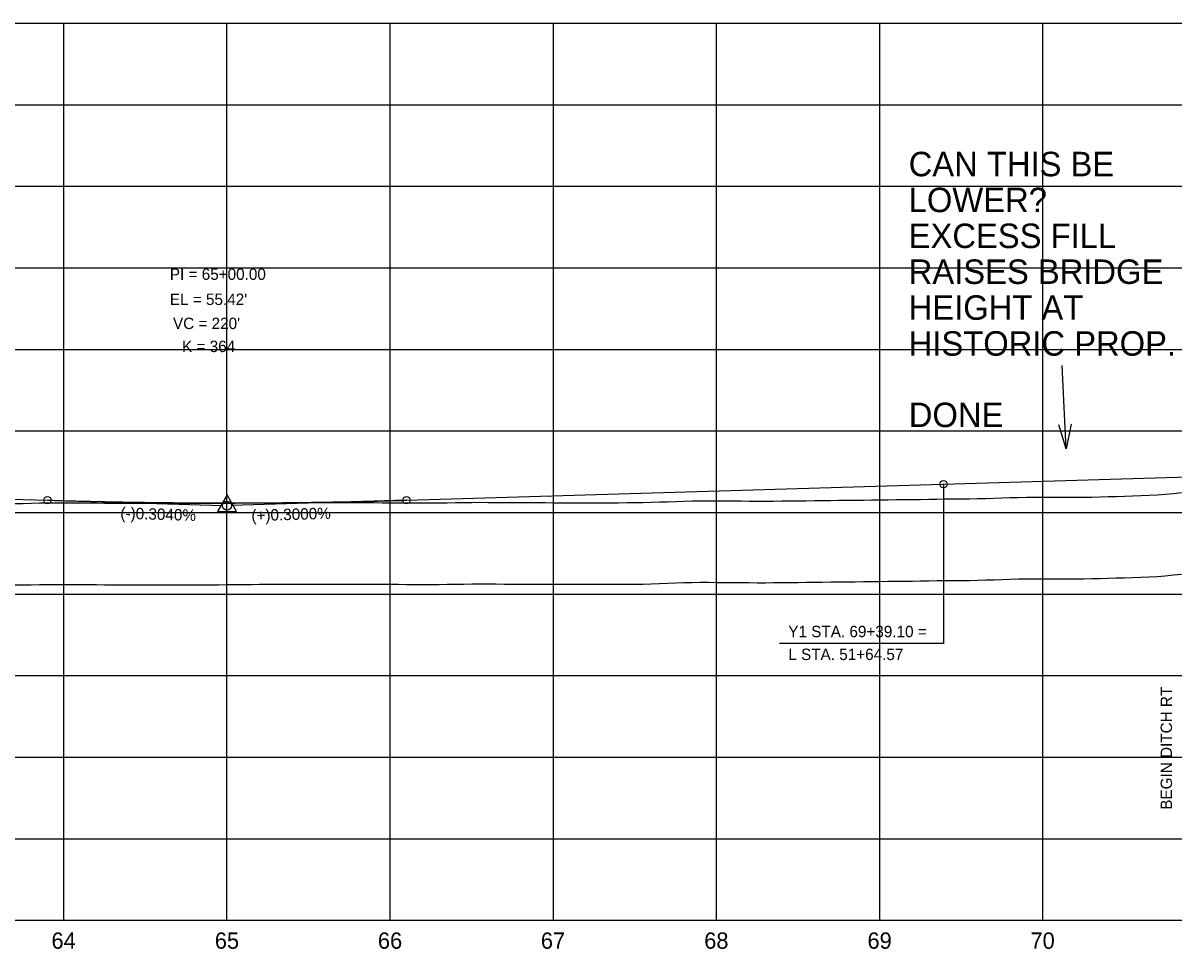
# Model space of a CAD drawing. Extents: x 2345490 to 2436403, y 465165 to 573888.
# Drawn here: x 2386697 to 2387402, y 557766 to 558334 of the extents above; entities that cross this region are included whole.
import ezdxf

# ---------------------------------------------------------------- set-up
doc = ezdxf.new("R2010")
doc.units = 0
for name, color, linetype in [('Old_Level_1', 7, 'Continuous'), ('Old_Level_2', 7, 'Continuous'), ('Old_Level_3', 7, 'Continuous'), ('Old_Level_57', 7, 'Continuous'), ('Old_Level_62', 7, 'Continuous'), ('Old_Level_63', 7, 'Continuous')]:
    doc.layers.add(name, color=color, linetype=linetype)

msp = doc.modelspace()

# ---------------------------------------------------------------- linework, layer by layer
at = {"layer": 'Old_Level_1'}
for points in [[(2387321.5425, 557993.43925), (2387326.5425, 557993.45375), (2387331.5425, 557993.47075), (2387336.5425, 557993.488), (2387341.5425, 557993.50525), (2387346.5425, 557993.52275), (2387351.5425, 557993.57775), (2387356.5425, 557993.6995), (2387361.5425, 557993.82175), (2387366.5425, 557993.944), (2387371.5425, 557994.09075), (2387376.5425, 557994.26875), (2387381.5425, 557994.44675), (2387386.5425, 557994.62475), (2387391.5425, 557994.88725), (2387396.5425, 557995.361), (2387401.5425, 557995.835), (2387406.5425, 557996.285)], [(2386691.5425, 557989.696), (2386696.5425, 557989.68025), (2386701.5425, 557989.834), (2386706.5425, 557989.99575), (2386711.5425, 557990.04875), (2386716.5425, 557990.04025), (2386721.5425, 557990.032), (2386726.5425, 557990.0235), (2386731.5425, 557990.015), (2386736.5425, 557989.99125), (2386741.5425, 557989.91625), (2386746.5425, 557989.84125), (2386751.5425, 557989.80225), (2386756.5425, 557989.784), (2386761.5425, 557989.766), (2386766.5425, 557989.748), (2386771.5425, 557989.73), (2386776.5425, 557989.7305), (2386781.5425, 557989.75425), (2386786.5425, 557989.778), (2386791.5425, 557989.7915), (2386796.5425, 557989.799), (2386801.5425, 557989.80675), (2386806.5425, 557989.8145), (2386811.5425, 557989.822), (2386816.5425, 557989.8345), (2386821.5425, 557989.8505)], [(2386821.5425, 557989.8505), (2386826.5425, 557989.86675), (2386831.5425, 557989.9185), (2386836.5425, 557989.991), (2386841.5425, 557990.06375), (2386846.5425, 557990.0945), (2386851.5425, 557990.10275), (2386856.5425, 557990.111), (2386861.5425, 557990.119), (2386866.5425, 557990.127), (2386871.5425, 557990.13), (2386876.5425, 557990.12975), (2386881.5425, 557990.1295), (2386886.5425, 557990.12925), (2386891.5425, 557990.129), (2386896.5425, 557990.13325), (2386901.5425, 557990.14075), (2386906.5425, 557990.148), (2386911.5425, 557990.135), (2386916.5425, 557990.11), (2386921.5425, 557990.08475), (2386926.5425, 557990.0595), (2386931.5425, 557990.03425), (2386936.5425, 557990.00875), (2386941.5425, 557989.9835), (2386946.5425, 557989.958), (2386951.5425, 557989.9935), (2386956.5425, 557990.065), (2386961.5425, 557990.1365), (2386966.5425, 557990.208), (2386971.5425, 557990.27925), (2386976.5425, 557990.32575), (2386981.5425, 557990.29525), (2386986.5425, 557990.2645), (2386991.5425, 557990.239), (2386996.5425, 557990.21675), (2387001.5425, 557990.1945), (2387006.5425, 557990.17225), (2387011.5425, 557990.15025), (2387016.5425, 557990.12825), (2387021.5425, 557990.10625), (2387026.5425, 557990.08425), (2387031.5425, 557990.0775), (2387036.5425, 557990.08025), (2387041.5425, 557990.083), (2387046.5425, 557990.08575), (2387051.5425, 557990.0885), (2387056.5425, 557990.09125), (2387061.5425, 557990.1145), (2387066.5425, 557990.156), (2387071.5425, 557990.1825), (2387076.5425, 557990.1995), (2387081.5425, 557990.362), (2387086.5425, 557990.542), (2387091.5425, 557990.7225), (2387096.5425, 557990.903), (2387101.5425, 557991.08375), (2387106.5425, 557991.26475), (2387111.5425, 557991.31775), (2387116.5425, 557991.2835), (2387121.5425, 557991.24975), (2387126.5425, 557991.216), (2387131.5425, 557991.18275), (2387136.5425, 557991.1495), (2387141.5425, 557991.1165), (2387146.5425, 557991.043), (2387151.5425, 557991.02075), (2387156.5425, 557991.083), (2387161.5425, 557991.1455), (2387166.5425, 557991.2085), (2387171.5425, 557991.27175), (2387176.5425, 557991.33525), (2387181.5425, 557991.39925), (2387186.5425, 557991.4635), (2387191.5425, 557991.5285), (2387196.5425, 557991.57175), (2387201.5425, 557991.62875), (2387206.5425, 557991.686), (2387211.5425, 557991.74375), (2387216.5425, 557991.802), (2387221.5425, 557991.8605), (2387226.5425, 557991.91975), (2387231.5425, 557991.9585), (2387236.5425, 557992.01875), (2387241.5425, 557992.0895), (2387246.5425, 557992.16075), (2387251.5425, 557992.23225), (2387256.5425, 557992.30425), (2387261.5425, 557992.3765), (2387266.5425, 557992.44925), (2387271.5425, 557992.4885), (2387276.5425, 557992.49), (2387281.5425, 557992.60775), (2387286.5425, 557992.75225), (2387291.5425, 557992.897), (2387296.5425, 557993.042), (2387301.5425, 557993.187), (2387306.5425, 557993.332), (2387311.5425, 557993.42025), (2387316.5425, 557993.42975), (2387321.5425, 557993.43925)]]:
    msp.add_lwpolyline(points, dxfattribs=at)
at = {"layer": 'Old_Level_2'}
for p, q in [((2386931.5425, 558041.61275), (2387441.5425, 558056.91275)), ((2386681.5425, 558042.569), (2386711.5425, 558041.65675)), ((2386711.5425, 558041.65675), (2386818.794, 558038.39625)), ((2386931.5425, 558041.61275), (2386824.2915, 558038.395))]:
    msp.add_line(p, q, dxfattribs=at)
msp.add_lwpolyline([(2386815.67725, 558034.739), (2386827.41975, 558034.739), (2386821.54875, 558044.86475)], close=True, dxfattribs=at)
for centre, radius in [((2387260.6425, 558051.48575), 2.25), ((2386711.5425, 558041.65675), 2.25), ((2386931.5425, 558041.61275), 2.25), ((2386821.5425, 558038.31275), 2.75)]:
    msp.add_circle(centre, radius, dxfattribs=at)
msp.add_spline([(2386711.5425, 558041.65675), (2386715.9425, 558041.52575), (2386720.3425, 558041.4), (2386724.7425, 558041.2795), (2386729.1425, 558041.16425), (2386733.5425, 558041.0545), (2386737.9425, 558040.95), (2386742.3425, 558040.85075), (2386746.7425, 558040.757), (2386751.1425, 558040.66825), (2386755.5425, 558040.585), (2386759.9425, 558040.507), (2386764.3425, 558040.4345), (2386768.7425, 558040.36725), (2386773.1425, 558040.305), (2386777.5425, 558040.2485), (2386781.9425, 558040.197), (2386786.3425, 558040.151), (2386790.7425, 558040.11025), (2386795.1425, 558040.07475), (2386799.5425, 558040.04475), (2386803.9425, 558040.02), (2386808.3425, 558040.0005), (2386812.7425, 558039.98625), (2386817.1425, 558039.9775), (2386821.5425, 558039.97375), (2386825.9425, 558039.97575), (2386830.3425, 558039.98275), (2386834.7425, 558039.99525), (2386839.1425, 558040.013), (2386843.5425, 558040.036), (2386847.9425, 558040.06425), (2386852.3425, 558040.098), (2386856.7425, 558040.137), (2386861.1425, 558040.18125), (2386865.5425, 558040.23075), (2386869.9425, 558040.28575), (2386874.3425, 558040.346), (2386878.7425, 558040.4115), (2386883.1425, 558040.4825), (2386887.5425, 558040.55875), (2386891.9425, 558040.64025), (2386896.3425, 558040.727), (2386900.7425, 558040.819), (2386905.1425, 558040.9165), (2386909.5425, 558041.01925), (2386913.9425, 558041.1275), (2386918.3425, 558041.24075), (2386922.7425, 558041.3595), (2386927.1425, 558041.4835), (2386931.5425, 558041.61275)], degree=3, dxfattribs=at)
at = {"layer": 'Old_Level_3'}
for p, q in [((2387260.6425, 558051.48575), (2387260.6425, 557953.83025)), ((2387260.6425, 557953.83025), (2387160.07325, 557953.83025))]:
    msp.add_line(p, q, dxfattribs=at)
at = {"layer": 'Old_Level_57'}
for p, q in [((2381271.54275, 558334.11325), (2393041.55275, 558334.11325)), ((2386721.54225, 557784.21325), (2386721.54225, 558334.21325)), ((2386721.54225, 557784.11325), (2386721.54225, 558334.11325)), ((2386821.54225, 557784.21325), (2386821.54225, 558334.21325)), ((2386821.54225, 557784.11325), (2386821.54225, 558334.11325)), ((2386921.54225, 557784.21325), (2386921.54225, 558334.21325)), ((2386921.54225, 557784.11325), (2386921.54225, 558334.11325)), ((2387021.54225, 557784.21325), (2387021.54225, 558334.21325)), ((2387021.54225, 557784.11325), (2387021.54225, 558334.11325)), ((2387121.54225, 557784.21325), (2387121.54225, 558334.21325)), ((2387121.54225, 557784.11325), (2387121.54225, 558334.11325)), ((2387221.54225, 557784.21325), (2387221.54225, 558334.21325)), ((2387221.54225, 557784.11325), (2387221.54225, 558334.11325)), ((2387321.54225, 557784.21325), (2387321.54225, 558334.21325)), ((2387321.54225, 557784.11325), (2387321.54225, 558334.11325)), ((2381271.54275, 558284.11325), (2393041.55275, 558284.11325)), ((2381271.54275, 558234.11325), (2393041.55275, 558234.11325)), ((2381271.54275, 558184.11325), (2393041.55275, 558184.11325)), ((2381271.54275, 558134.11325), (2393041.55275, 558134.11325)), ((2381271.54275, 558084.11325), (2393041.55275, 558084.11325)), ((2381271.5425, 558034.11325), (2393041.55275, 558034.11325)), ((2381271.54275, 557984.11325), (2393041.55275, 557984.11325)), ((2381271.5425, 557934.11325), (2393041.55275, 557934.11325)), ((2381271.54275, 557884.11325), (2393041.55275, 557884.11325)), ((2381271.5425, 557834.11325), (2393041.55275, 557834.11325)), ((2381271.54275, 557784.11325), (2393041.55275, 557784.11325))]:
    msp.add_line(p, q, dxfattribs=at)
at = {"layer": 'Old_Level_62'}
for points in [[(2387321.5425, 558043.44525), (2387326.5425, 558043.45975), (2387331.5425, 558043.47675), (2387336.5425, 558043.494), (2387341.5425, 558043.51125), (2387346.5425, 558043.52875), (2387351.5425, 558043.58375), (2387356.5425, 558043.7055), (2387361.5425, 558043.82775), (2387366.5425, 558043.95), (2387371.5425, 558044.09675), (2387376.5425, 558044.27475), (2387381.5425, 558044.45275), (2387386.5425, 558044.63075), (2387391.5425, 558044.89325), (2387396.5425, 558045.367), (2387401.5425, 558045.841), (2387406.5425, 558046.291)], [(2386691.5425, 558039.702), (2386696.5425, 558039.68625), (2386701.5425, 558039.84), (2386706.5425, 558040.00175), (2386711.5425, 558040.05475), (2386716.5425, 558040.04625), (2386721.5425, 558040.038), (2386726.5425, 558040.0295), (2386731.5425, 558040.021), (2386736.5425, 558039.99725), (2386741.5425, 558039.92225), (2386746.5425, 558039.84725), (2386751.5425, 558039.80825), (2386756.5425, 558039.79), (2386761.5425, 558039.772), (2386766.5425, 558039.754), (2386771.5425, 558039.736), (2386776.5425, 558039.7365), (2386781.5425, 558039.76025), (2386786.5425, 558039.784), (2386791.5425, 558039.7975), (2386796.5425, 558039.805), (2386801.5425, 558039.81275), (2386806.5425, 558039.8205), (2386811.5425, 558039.828), (2386816.5425, 558039.8405), (2386821.5425, 558039.8565)], [(2386821.5425, 558039.8565), (2386826.5425, 558039.87275), (2386831.5425, 558039.9245), (2386836.5425, 558039.997), (2386841.5425, 558040.06975), (2386846.5425, 558040.1005), (2386851.5425, 558040.10875), (2386856.5425, 558040.117), (2386861.5425, 558040.125), (2386866.5425, 558040.133), (2386871.5425, 558040.136), (2386876.5425, 558040.13575), (2386881.5425, 558040.1355), (2386886.5425, 558040.13525), (2386891.5425, 558040.135), (2386896.5425, 558040.13925), (2386901.5425, 558040.14675), (2386906.5425, 558040.154), (2386911.5425, 558040.141), (2386916.5425, 558040.116), (2386921.5425, 558040.09075), (2386926.5425, 558040.0655), (2386931.5425, 558040.04025), (2386936.5425, 558040.01475), (2386941.5425, 558039.9895), (2386946.5425, 558039.964), (2386951.5425, 558039.9995), (2386956.5425, 558040.071), (2386961.5425, 558040.1425), (2386966.5425, 558040.214), (2386971.5425, 558040.28525), (2386976.5425, 558040.33175), (2386981.5425, 558040.30125), (2386986.5425, 558040.2705), (2386991.5425, 558040.245), (2386996.5425, 558040.22275), (2387001.5425, 558040.2005), (2387006.5425, 558040.17825), (2387011.5425, 558040.15625), (2387016.5425, 558040.13425), (2387021.5425, 558040.11225), (2387026.5425, 558040.09025), (2387031.5425, 558040.0835), (2387036.5425, 558040.08625), (2387041.5425, 558040.089), (2387046.5425, 558040.09175), (2387051.5425, 558040.0945), (2387056.5425, 558040.09725), (2387061.5425, 558040.1205), (2387066.5425, 558040.162), (2387071.5425, 558040.1885), (2387076.5425, 558040.2055), (2387081.5425, 558040.368), (2387086.5425, 558040.548), (2387091.5425, 558040.7285), (2387096.5425, 558040.909), (2387101.5425, 558041.08975), (2387106.5425, 558041.27075), (2387111.5425, 558041.32375), (2387116.5425, 558041.2895), (2387121.5425, 558041.25575), (2387126.5425, 558041.222), (2387131.5425, 558041.18875), (2387136.5425, 558041.1555), (2387141.5425, 558041.1225), (2387146.5425, 558041.049), (2387151.5425, 558041.02675), (2387156.5425, 558041.089), (2387161.5425, 558041.1515), (2387166.5425, 558041.2145), (2387171.5425, 558041.27775), (2387176.5425, 558041.34125), (2387181.5425, 558041.40525), (2387186.5425, 558041.4695), (2387191.5425, 558041.5345), (2387196.5425, 558041.57775), (2387201.5425, 558041.63475), (2387206.5425, 558041.692), (2387211.5425, 558041.74975), (2387216.5425, 558041.808), (2387221.5425, 558041.8665), (2387226.5425, 558041.92575), (2387231.5425, 558041.9645), (2387236.5425, 558042.02475), (2387241.5425, 558042.0955), (2387246.5425, 558042.16675), (2387251.5425, 558042.23825), (2387256.5425, 558042.31025), (2387261.5425, 558042.3825), (2387266.5425, 558042.45525), (2387271.5425, 558042.4945), (2387276.5425, 558042.496), (2387281.5425, 558042.61375), (2387286.5425, 558042.75825), (2387291.5425, 558042.903), (2387296.5425, 558043.048), (2387301.5425, 558043.193), (2387306.5425, 558043.338), (2387311.5425, 558043.42625), (2387316.5425, 558043.43575), (2387321.5425, 558043.44525)]]:
    msp.add_lwpolyline(points, dxfattribs=at)
at = {"layer": 'Old_Level_63'}
for p, q in [((2387335.7365, 558073.02975), (2387333.4405, 558124.324)), ((2381321.5425, 557784.113), (2393019.104, 557784.113))]:
    msp.add_line(p, q, dxfattribs=at)
msp.add_lwpolyline([(2387338.812, 558088.1825), (2387335.7365, 558073.02975), (2387331.3195, 558087.847)], dxfattribs=at)

# ---------------------------------------------------------------- texts
at = {"layer": 'Old_Level_1'}
for s, p in [('64', (2386713.994, 557766.613)), ('65', (2386814.0865, 557766.613)), ('66', (2386914.0275, 557766.613)), ('67', (2387013.885, 557766.613)), ('68', (2387114.01075, 557766.613)), ('69', (2387214.053, 557766.613)), ('70', (2387313.929, 557766.613))]:
    msp.add_text(s, height=10.000001, dxfattribs=at).set_placement(p)
at = {"layer": 'Old_Level_2'}
for s, height, p in [('PI = 65+00.00', 7.0000005, (2386786.54275, 558176.71775)), ("EL = 55.42'", 7.0000005, (2386786.5425, 558161.31275)), ("VC = 220'", 7.000001, (2386788.4585, 558146.55975)), ('K = 364', 7.000001, (2386794.03875, 558132.445))]:
    msp.add_text(s, height=height, dxfattribs=at).set_placement(p)
for s, rotation, p in [('(-)0.3040%', 358.25874444, (2386756.14, 558030.296)), ('(+)0.3000%', 1.71835833, (2386836.5965, 558028.7595))]:
    msp.add_text(s, height=7.000001, rotation=rotation, dxfattribs=at).set_placement(p)
at = {"layer": 'Old_Level_3'}
for s, p in [('Y1 STA. 69+39.10 =', (2387165.516, 557957.6265)), ('L STA. 51+64.57', (2387165.516, 557943.62625))]:
    msp.add_text(s, height=7.0000005, dxfattribs=at).set_placement(p)
msp.add_text('BEGIN DITCH RT', height=7.0000005, rotation=90, dxfattribs=at).set_placement((2387400.6787, 557851.85205))
at = {"layer": 'Old_Level_63'}
for s, p in [('CAN THIS BE', (2387239.30275, 558240.239)), ('LOWER? ', (2387239.30275, 558218.239)), ('EXCESS FILL ', (2387239.30275, 558196.239)), ('RAISES BRIDGE', (2387239.30275, 558174.239)), ('HEIGHT AT', (2387239.30275, 558152.239)), ('HISTORIC PROP.', (2387239.30275, 558130.239)), ('DONE', (2387239.35525, 558086.45475))]:
    msp.add_text(s, height=15, dxfattribs=at).set_placement(p)

doc.saveas('drawing.dxf')
